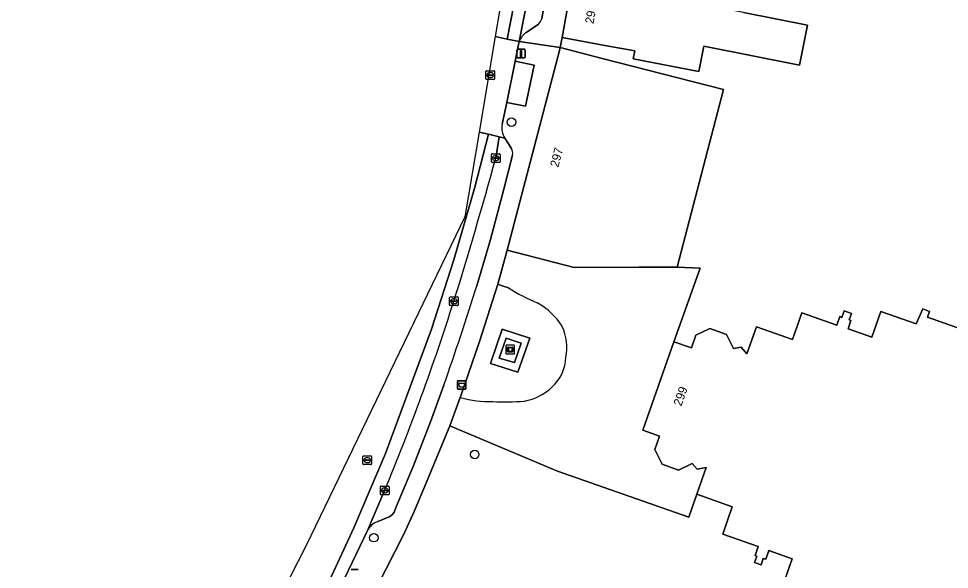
# Model space of a CAD drawing. Extents: x 160157 to 160921, y 381516 to 382045.
# Drawn here: x 160221.3 to 160328.3, y 381786.4 to 381849.8 of the extents above; entities that cross this region are included whole.
import ezdxf

# ---------------------------------------------------------------- set-up
doc = ezdxf.new("R2010")
doc.units = 0
for name, color, linetype in [('IMGEO_Afvalbak', 7, 'Continuous'), ('IMGEO_Boom', 7, 'Continuous'), ('IMGEO_Erf', 7, 'Continuous'), ('IMGEO_Grasland_overig', 7, 'Continuous'), ('IMGEO_Groenvoorziening', 7, 'Continuous'), ('IMGEO_Kolk', 7, 'Continuous'), ('IMGEO_Kunstobject', 7, 'Continuous'), ('IMGEO_Lichtmast', 7, 'Continuous'), ('IMGEO_Muur', 7, 'Continuous'), ('IMGEO_Pand', 7, 'Continuous'), ('IMGEO_Pand_nummerreeks', 7, 'Continuous'), ('IMGEO_Parkeervlak_open', 7, 'Continuous'), ('IMGEO_Rijbaan_lokaal_gesloten', 7, 'Continuous'), ('IMGEO_Rijbaan_lokaal_open', 7, 'Continuous'), ('IMGEO_Rioolput', 7, 'Continuous'), ('IMGEO_Terreindeel_gesloten', 7, 'Continuous'), ('IMGEO_Voetpad_open', 7, 'Continuous')]:
    doc.layers.add(name, color=color, linetype=linetype)

msp = doc.modelspace()

# ---------------------------------------------------------------- linework, layer by layer
at = {"layer": 'IMGEO_Afvalbak'}
for p, q in [((160271.85, 381808.13), (160272.64, 381808.13)), ((160272.64, 381808.13), (160271.85, 381808.13)), ((160271.75, 381807.24), (160271.75, 381808.03)), ((160271.75, 381808.03), (160271.75, 381807.24)), ((160272.64, 381807.14), (160271.85, 381807.14)), ((160271.85, 381807.14), (160272.64, 381807.14)), ((160272.74, 381808.03), (160272.74, 381807.24)), ((160272.74, 381807.24), (160272.74, 381808.03))]:
    msp.add_line(p, q, dxfattribs=at)
msp.add_lwpolyline([(160271.89, 381807.85), (160272.6, 381807.85), (160272.45, 381807.38), (160272.04, 381807.38), (160271.89, 381807.85)], dxfattribs=at)
for centre, start, end in [((160271.85, 381808.03), 90, 180), ((160271.85, 381808.03), 90, 180), ((160272.64, 381808.03), 0, 90), ((160272.64, 381808.03), 360, 90), ((160271.85, 381807.24), 180, 270), ((160271.85, 381807.24), 180, 270), ((160272.64, 381807.24), 270, 0), ((160272.64, 381807.24), 270, 0)]:
    msp.add_arc(centre, 0.1, start, end, dxfattribs=at)
at = {"layer": 'IMGEO_Boom'}
for centre in [(160277.98, 381837.86), (160273.74, 381799.65), (160262.15, 381790.08)]:
    msp.add_circle(centre, 0.489, dxfattribs=at)
at = {"layer": 'IMGEO_Erf'}
for points in [[(160304.64, 381850.46), (160311.98, 381849.02), (160311.07, 381844.42), (160300.06, 381846.58), (160299.49, 381843.66), (160291.95, 381845.14), (160292.13, 381846.07), (160288.71, 381846.67), (160283.79, 381847.6), (160283.57, 381846.42), (160288.39, 381845.18), (160302.32, 381841.61), (160297.01, 381821.2), (160299.65, 381821.06), (160296.64, 381812.6), (160298.66, 381811.9), (160299.17, 381813.36), (160300.78, 381814.13), (160302.69, 381813.46), (160303.48, 381811.83), (160304.36, 381812), (160305.03, 381811.22), (160306.12, 381814.32), (160310.27, 381812.86), (160311.35, 381815.94), (160315.36, 381814.53), (160315.7, 381815.5), (160315.95, 381815.41), (160316.21, 381816.16), (160317.04, 381815.86), (160316.79, 381815.13), (160316.99, 381815.06), (160316.65, 381814.08), (160319.39, 381813.12), (160320.43, 381816.08), (160324.47, 381814.66), (160325.23, 381816.38), (160326.02, 381816.1), (160325.79, 381815.43), (160330.23, 381813.88)], [(160309.15, 381784.6), (160310.23, 381787.66), (160307.54, 381788.6), (160307.19, 381787.6), (160306.9, 381787.7), (160306.65, 381786.98), (160305.9, 381787.24), (160306.15, 381787.96), (160305.96, 381788.04), (160306.32, 381789.07), (160302.25, 381790.5), (160303.35, 381793.64), (160299.27, 381795.07), (160298.35, 381792.45), (160283.25, 381797.74), (160270.9, 381802.95), (160268.19, 381796.46), (160266.77, 381793.11), (160265.61, 381790.49), (160253.12, 381765.96)]]:
    msp.add_lwpolyline(points, dxfattribs=at)
at = {"layer": 'IMGEO_Grasland_overig'}
for points in [[(160280.06, 381813.02), (160276.91, 381814.07), (160275.57, 381810.11), (160278.71, 381809.13)], [(160278.32, 381810.22), (160276.57, 381810.73), (160277.36, 381813.02), (160279.1, 381812.44)]]:
    msp.add_lwpolyline(points, close=True, dxfattribs=at)
at = {"layer": 'IMGEO_Groenvoorziening'}
msp.add_lwpolyline([(160277.62, 381818.81), (160276.91, 381819.04), (160276.39, 381819.22), (160274.31, 381812.62), (160272.16, 381806.4), (160272.09, 381806.2)], dxfattribs=at)
msp.add_lwpolyline([(160278.71, 381809.13), (160275.57, 381810.11), (160276.91, 381814.07), (160280.06, 381813.02)], close=True, dxfattribs=at)
for centre, radius, start, end in [((160290.22, 381838.73), 23.57, 237.6808, 246.7935), ((160277.27, 381810.3), 7.7, 32.0173, 61.5728), ((160278.48, 381811.97), 5.84, 348.6439, 24.3229), ((160279.41, 381810.97), 4.8, 312.6367, 358.2842), ((160278.4, 381811.79), 6.09, 279.9736, 314.4215), ((160275.63, 381819.2), 13.47, 254.7813, 270.825), ((160277.11, 381835.99), 30.29, 267.5557, 274.4318)]:
    msp.add_arc(centre, radius, start, end, dxfattribs=at)
at = {"layer": 'IMGEO_Kolk'}
for p, q in [((160275.66, 381833.28), (160275.66, 381834.14)), ((160275.74, 381834.21), (160276.59, 381834.21)), ((160276.15, 381833.99), (160276.18, 381833.99)), ((160276.66, 381834.14), (160276.66, 381833.28)), ((160276.59, 381833.21), (160275.74, 381833.21)), ((160275.92, 381833.7), (160275.92, 381833.72)), ((160276.36, 381833.67), (160275.96, 381833.67)), ((160275.97, 381833.75), (160276.36, 381833.75)), ((160276.17, 381833.43), (160276.15, 381833.43)), ((160276.41, 381833.72), (160276.41, 381833.7)), ((160270.93, 381817.76), (160271.78, 381817.76)), ((160270.85, 381816.84), (160270.85, 381817.69)), ((160271.78, 381816.76), (160270.93, 381816.76)), ((160271.11, 381817.26), (160271.11, 381817.27)), ((160271.15, 381817.31), (160271.55, 381817.31)), ((160271.55, 381817.22), (160271.15, 381817.22)), ((160271.34, 381817.54), (160271.36, 381817.54)), ((160271.36, 381816.98), (160271.34, 381816.98)), ((160271.59, 381817.27), (160271.59, 381817.26)), ((160271.85, 381817.69), (160271.85, 381816.84)), ((160262.9, 381795.09), (160262.9, 381795.94)), ((160262.97, 381796.02), (160263.83, 381796.02)), ((160263.16, 381795.51), (160263.16, 381795.52)), ((160263.2, 381795.56), (160263.6, 381795.56)), ((160263.59, 381795.47), (160263.2, 381795.47)), ((160263.39, 381795.8), (160263.41, 381795.8)), ((160263.64, 381795.52), (160263.64, 381795.51)), ((160263.9, 381795.94), (160263.9, 381795.09)), ((160263.83, 381795.02), (160262.97, 381795.02)), ((160263.41, 381795.24), (160263.38, 381795.24))]:
    msp.add_line(p, q, dxfattribs=at)
for points in [[(160275.66, 381833.28), (160275.66, 381834.14)], [(160275.74, 381834.21), (160276.59, 381834.21)], [(160276.66, 381834.14), (160276.66, 381833.28)], [(160276.59, 381833.21), (160275.74, 381833.21)], [(160270.93, 381817.76), (160271.78, 381817.76)], [(160270.85, 381816.84), (160270.85, 381817.69)], [(160271.78, 381816.76), (160270.93, 381816.76)], [(160271.85, 381817.69), (160271.85, 381816.84)], [(160262.9, 381795.09), (160262.9, 381795.94)], [(160262.97, 381796.02), (160263.83, 381796.02)], [(160263.9, 381795.94), (160263.9, 381795.09)], [(160263.83, 381795.02), (160262.97, 381795.02)]]:
    msp.add_lwpolyline(points, dxfattribs=at)
for centre, radius, start, end in [((160275.74, 381834.14), 0.0765, 91.552, 178.448), ((160275.74, 381834.14), 0.0765, 91.552, 178.448), ((160276.59, 381834.14), 0.0765, 1.552, 88.448), ((160276.59, 381834.14), 0.0765, 1.552, 88.448), ((160275.74, 381833.29), 0.0765, 181.552, 268.448), ((160275.74, 381833.29), 0.0765, 181.552, 268.448), ((160275.96, 381833.71), 0.0403, 85.8775, 175.7526), ((160275.96, 381833.7), 0.0366, 178.938, 274.7102), ((160276.37, 381833.72), 0.0386, 1.7309, 96.639), ((160276.36, 381833.71), 0.043, 264.8664, 352.4533), ((160276.59, 381833.29), 0.0765, 271.552, 358.448), ((160276.59, 381833.29), 0.0765, 271.552, 358.448), ((160270.93, 381817.69), 0.0765, 91.552, 178.448), ((160270.93, 381817.69), 0.0765, 91.552, 178.448), ((160271.78, 381817.69), 0.0765, 1.552, 88.448), ((160271.78, 381817.69), 0.0765, 1.552, 88.448), ((160270.93, 381816.84), 0.0765, 181.552, 268.448), ((160270.93, 381816.84), 0.0765, 181.552, 268.448), ((160271.15, 381817.27), 0.0403, 85.8775, 175.7526), ((160271.15, 381817.26), 0.0366, 178.938, 274.7102), ((160271.56, 381817.27), 0.0386, 1.7309, 96.639), ((160271.55, 381817.26), 0.043, 264.8664, 352.4533), ((160271.78, 381816.84), 0.0765, 271.552, 358.448), ((160271.78, 381816.84), 0.0765, 271.552, 358.448), ((160262.97, 381795.94), 0.0765, 91.552, 178.448), ((160262.97, 381795.94), 0.0765, 91.552, 178.448), ((160263.2, 381795.52), 0.0403, 85.8775, 175.7526), ((160263.19, 381795.51), 0.0366, 178.938, 274.7102), ((160263.6, 381795.52), 0.043, 264.8664, 352.4533), ((160263.6, 381795.52), 0.0386, 1.7309, 96.639), ((160263.82, 381795.94), 0.0765, 1.552, 88.448), ((160263.82, 381795.94), 0.0765, 1.552, 88.448), ((160262.97, 381795.09), 0.0765, 181.552, 268.448), ((160262.97, 381795.09), 0.0765, 181.552, 268.448), ((160263.82, 381795.09), 0.0765, 271.552, 358.448), ((160263.82, 381795.09), 0.0765, 271.552, 358.448)]:
    msp.add_arc(centre, radius, start, end, dxfattribs=at)
for centre, major_axis, ratio, start_param, end_param in [((160276.15, 381833.71), (-0.387, 0.002), 0.722429, 4.712389, 7.853982), ((160276.17, 381833.71), (-0.39, 0.002), 0.717154, 1.570796, 4.712389), ((160271.34, 381817.26), (-0.387, 0.002), 0.722429, 4.712389, 7.853982), ((160271.36, 381817.26), (-0.39, 0.002), 0.717154, 1.570796, 4.712389), ((160263.39, 381795.52), (-0.387, 0.002), 0.722429, 4.712389, 7.853982), ((160263.41, 381795.52), (-0.39, 0.002), 0.717154, 1.570796, 4.712389)]:
    msp.add_ellipse(centre, major_axis=major_axis, ratio=ratio, start_param=start_param, end_param=end_param, dxfattribs=at)
at = {"layer": 'IMGEO_Kunstobject'}
for p, q in [((160277.32, 381812.13), (160277.32, 381811.29)), ((160277.32, 381812.13), (160277.32, 381811.29)), ((160278.24, 381812.21), (160277.4, 381812.21)), ((160278.24, 381812.21), (160277.4, 381812.21)), ((160277.53, 381811.48), (160277.53, 381811.95)), ((160277.58, 381812), (160278.06, 381812)), ((160278.06, 381811.43), (160277.58, 381811.43)), ((160277.61, 381811.9), (160277.61, 381811.53)), ((160278.01, 381811.92), (160277.63, 381811.92)), ((160277.63, 381811.51), (160278.01, 381811.51)), ((160278.03, 381811.53), (160278.03, 381811.9)), ((160278.11, 381811.95), (160278.11, 381811.48)), ((160278.32, 381811.3), (160278.32, 381812.14)), ((160278.32, 381811.3), (160278.32, 381812.14)), ((160277.41, 381811.21), (160278.25, 381811.21)), ((160277.41, 381811.21), (160278.25, 381811.21))]:
    msp.add_line(p, q, dxfattribs=at)
for centre, radius, start, end in [((160277.4, 381812.13), 0.0779, 92.4484, 184.2845), ((160277.4, 381812.13), 0.0779, 92.4484, 184.2845), ((160277.58, 381811.95), 0.05, 90, 180), ((160277.58, 381811.48), 0.05, 180, 270), ((160277.63, 381811.9), 0.02, 90, 180), ((160277.63, 381811.53), 0.02, 180, 270), ((160278.01, 381811.9), 0.02, 360, 90), ((160278.01, 381811.53), 0.02, 270, 0), ((160278.06, 381811.95), 0.05, 360, 90), ((160278.06, 381811.48), 0.05, 270, 0), ((160278.24, 381812.13), 0.0779, 2.4484, 94.2845), ((160278.24, 381812.13), 0.0779, 2.4484, 94.2845), ((160277.4, 381811.29), 0.0779, 182.4484, 274.2845), ((160277.4, 381811.29), 0.0779, 182.4484, 274.2845), ((160278.24, 381811.29), 0.0779, 272.4484, 4.2845), ((160278.24, 381811.29), 0.0779, 272.4484, 4.2845)]:
    msp.add_arc(centre, radius, start, end, dxfattribs=at)
at = {"layer": 'IMGEO_Lichtmast'}
for p, q in [((160278.57, 381845.34), (160278.57, 381846.13)), ((160278.57, 381846.13), (160278.57, 381845.34)), ((160278.67, 381846.23), (160279.46, 381846.23)), ((160279.46, 381846.23), (160278.67, 381846.23)), ((160279.56, 381846.13), (160279.56, 381845.34)), ((160279.56, 381845.34), (160279.56, 381846.13)), ((160279.46, 381845.24), (160278.67, 381845.24)), ((160278.67, 381845.24), (160279.46, 381845.24)), ((160259.56, 381786.44), (160260.34, 381786.44)), ((160260.34, 381786.44), (160259.56, 381786.44))]:
    msp.add_line(p, q, dxfattribs=at)
msp.add_lwpolyline([(160278.99, 381846.11), (160279.14, 381846.11), (160279.14, 381845.36), (160278.99, 381845.36), (160278.99, 381846.11)], dxfattribs=at)
for centre, start, end in [((160278.67, 381846.13), 90, 180), ((160278.67, 381846.13), 90, 180), ((160279.46, 381846.13), 0, 90), ((160279.46, 381846.13), 360, 90), ((160278.67, 381845.34), 180, 270), ((160278.67, 381845.34), 180, 270), ((160279.46, 381845.34), 270, 0), ((160279.46, 381845.34), 270, 0)]:
    msp.add_arc(centre, 0.1, start, end, dxfattribs=at)
at = {"layer": 'IMGEO_Muur'}
for points in [[(160276.39, 381819.22), (160274.31, 381812.62), (160272.16, 381806.4), (160272.09, 381806.2)], [(160268.19, 381796.46), (160270.9, 381802.95)], [(160253.12, 381765.96), (160265.61, 381790.49), (160266.77, 381793.11)]]:
    msp.add_lwpolyline(points, dxfattribs=at)
at = {"layer": 'IMGEO_Pand'}
for points in [[(160311.98, 381849.02), (160304.64, 381850.46), (160302.06, 381850.97), (160299.88, 381851.39), (160293.38, 381852.67), (160293.08, 381852.73), (160293.14, 381853.09), (160285.02, 381854.49), (160283.79, 381847.6), (160288.71, 381846.67), (160292.13, 381846.07), (160291.95, 381845.14), (160299.49, 381843.66), (160300.06, 381846.58), (160311.07, 381844.42)], [(160283.57, 381846.42), (160283.49, 381846.11), (160277.48, 381823.12), (160285.16, 381821.16), (160292.59, 381821.19), (160292.78, 381821.19), (160297.01, 381821.2), (160302.32, 381841.61), (160288.39, 381845.18)]]:
    msp.add_lwpolyline(points, close=True, dxfattribs=at)
msp.add_lwpolyline([(160330.23, 381813.88), (160325.79, 381815.43), (160326.02, 381816.1), (160325.23, 381816.38), (160324.47, 381814.66), (160320.43, 381816.08), (160319.39, 381813.12), (160316.65, 381814.08), (160316.99, 381815.06), (160316.79, 381815.13), (160317.04, 381815.86), (160316.21, 381816.16), (160315.95, 381815.41), (160315.7, 381815.5), (160315.36, 381814.53), (160311.35, 381815.94), (160310.27, 381812.86), (160306.12, 381814.32), (160305.03, 381811.22), (160304.36, 381812), (160303.48, 381811.83), (160302.69, 381813.46), (160300.78, 381814.13), (160299.17, 381813.36), (160298.66, 381811.9), (160296.64, 381812.6), (160293.07, 381802.43), (160295, 381801.75), (160294.46, 381800.23), (160295.29, 381798.52), (160297.15, 381797.86), (160298.74, 381798.62), (160299.31, 381797.96), (160300.35, 381798.15), (160299.27, 381795.07), (160303.35, 381793.64), (160302.25, 381790.5), (160306.32, 381789.07), (160305.96, 381788.04), (160306.15, 381787.96), (160305.9, 381787.24), (160306.65, 381786.98), (160306.9, 381787.7), (160307.19, 381787.6), (160307.54, 381788.6), (160310.23, 381787.66), (160309.15, 381784.6)], dxfattribs=at)
at = {"layer": 'IMGEO_Parkeervlak_open'}
for points in [[(160282.32, 381865.78), (160280.45, 381855.34), (160278.87, 381847.11)], [(160281.46, 381849.76), (160283.72, 381862.41)], [(160279.73, 381848.2), (160281.07, 381849.13)], [(160277.96, 381834.84), (160277.19, 381836.03), (160276.55, 381836.18), (160276.16, 381833.71)], [(160273.97, 381819.05), (160275.56, 381824.35), (160277.11, 381830.16), (160278.08, 381834.07)], [(160262.53, 381791.92), (160263.93, 381792.5), (160264.25, 381792.73), (160264.49, 381793.02), (160264.73, 381793.62), (160266.66, 381798.25), (160268.65, 381803.39), (160270.19, 381807.62)], [(160263.39, 381795.52), (160261.41, 381790.91)]]:
    msp.add_lwpolyline(points, dxfattribs=at)
msp.add_lwpolyline([(160280.57, 381844.42), (160278.4, 381844.86), (160277.43, 381840.12), (160279.58, 381839.7)], close=True, dxfattribs=at)
for centre, radius, start, end in [((160280.38, 381849.99), 1.1, 308.3584, 347.7613), ((160280.85, 381846.44), 2.09, 122.4168, 161.2549), ((160277.16, 381834.31), 0.951, 345.1327, 33.6957), ((159797.9, 381964.7), 495.87, 342.7026, 344.6829), ((159969.33, 381913.56), 318.97, 340.603, 342.7649), ((160017.57, 381897.75), 266.23, 337.4183, 342.4028), ((160263.35, 381789.88), 2.19, 111.9125, 151.9314)]:
    msp.add_arc(centre, radius, start, end, dxfattribs=at)
at = {"layer": 'IMGEO_Rijbaan_lokaal_gesloten'}
for points in [[(160276.11, 381847.71), (160277.47, 381847.41), (160279.43, 381857.4), (160281.06, 381866.83), (160283.01, 381877.48), (160287.95, 381901.47), (160291.03, 381915.39), (160292.66, 381923.46), (160295.11, 381937.88), (160297.52, 381953.39), (160298.83, 381953.2), (160299.47, 381957.15), (160299.62, 381958.1), (160298.28, 381958.32), (160297.16, 381958.5), (160297.16, 381958.5), (160296.82, 381956.93), (160291.86, 381933.88), (160277.86, 381858.1)], [(160221.32, 381724.92), (160224.38, 381723.35), (160226.13, 381726.77), (160238.68, 381750.08), (160245.71, 381763.32), (160252.51, 381776.06), (160256.59, 381784.17), (160259.85, 381791.2), (160263.48, 381799.77), (160268.78, 381814.05), (160271.36, 381822.03), (160273.77, 381830.38), (160275.32, 381836.47), (160274.26, 381836.72), (160274.26, 381836.72), (160272.62, 381826.97), (160254.37, 381789.2), (160234.62, 381750.43)]]:
    msp.add_lwpolyline(points, close=True, dxfattribs=at)
for points in [[(160279.43, 381857.4), (160277.47, 381847.41), (160278.87, 381847.11), (160280.45, 381855.34)], [(160276.91, 381837.61), (160277.43, 381840.12), (160278.4, 381844.86), (160278.83, 381846.97), (160278.87, 381847.11), (160277.47, 381847.41), (160276.11, 381847.71), (160274.26, 381836.72)], [(160276.16, 381833.71), (160276.55, 381836.18), (160275.32, 381836.47), (160273.77, 381830.38), (160271.36, 381822.03), (160268.78, 381814.05), (160263.48, 381799.77), (160259.85, 381791.2), (160256.59, 381784.17), (160252.51, 381776.06), (160245.71, 381763.32), (160238.68, 381750.08), (160226.13, 381726.77), (160224.38, 381723.35), (160225.65, 381722.7), (160227.87, 381726.9), (160234.08, 381738.56), (160237.37, 381744.72), (160239.23, 381748.15), (160240.22, 381750), (160248.02, 381764.54)], [(160274.26, 381836.72), (160274.26, 381836.72), (160275.32, 381836.47), (160276.55, 381836.18), (160277.19, 381836.03)], [(160248.02, 381764.54), (160254.74, 381777.2), (160257.05, 381781.79), (160261.41, 381790.91), (160263.39, 381795.52)]]:
    msp.add_lwpolyline(points, dxfattribs=at)
for centre, radius, start, end in [((160278.92, 381837.14), 2.06, 167.0279, 212.7345), ((159797.9, 381964.7), 495.87, 342.7026, 344.6829), ((160017.57, 381897.75), 266.23, 337.4183, 342.4028)]:
    msp.add_arc(centre, radius, start, end, dxfattribs=at)
at = {"layer": 'IMGEO_Rijbaan_lokaal_open'}
for points in [[(160296.64, 381812.6), (160299.65, 381821.06), (160297.01, 381821.2), (160292.78, 381821.19), (160292.59, 381821.19), (160285.16, 381821.16), (160277.48, 381823.12), (160276.39, 381819.22), (160276.91, 381819.04), (160277.62, 381818.81)], [(160272.09, 381806.2), (160270.9, 381802.95), (160283.25, 381797.74), (160298.35, 381792.45), (160299.27, 381795.07), (160300.35, 381798.15), (160299.31, 381797.96), (160298.74, 381798.62), (160297.15, 381797.86), (160295.29, 381798.52), (160294.46, 381800.23), (160295, 381801.75), (160293.07, 381802.43), (160296.64, 381812.6)]]:
    msp.add_lwpolyline(points, dxfattribs=at)
for centre, radius, start, end in [((160290.22, 381838.73), 23.57, 237.6808, 246.7935), ((160277.27, 381810.3), 7.7, 32.0173, 61.5728), ((160278.48, 381811.97), 5.84, 348.6439, 24.3229), ((160279.41, 381810.97), 4.8, 312.6367, 358.2842), ((160278.4, 381811.79), 6.09, 279.9736, 314.4215), ((160275.63, 381819.2), 13.47, 254.7813, 270.825), ((160277.11, 381835.99), 30.29, 267.5557, 274.4318)]:
    msp.add_arc(centre, radius, start, end, dxfattribs=at)
at = {"layer": 'IMGEO_Rioolput'}
for p, q in [((160275.03, 381842.84), (160275.03, 381843.7)), ((160275.1, 381843.77), (160275.95, 381843.77)), ((160275.51, 381843.55), (160275.54, 381843.55)), ((160276.03, 381843.7), (160276.03, 381842.84)), ((160275.95, 381842.77), (160275.1, 381842.77)), ((160275.28, 381843.26), (160275.28, 381843.28)), ((160275.72, 381843.23), (160275.32, 381843.23)), ((160275.33, 381843.31), (160275.73, 381843.31)), ((160275.54, 381842.99), (160275.51, 381842.99)), ((160275.77, 381843.28), (160275.77, 381843.26)), ((160260.89, 381798.56), (160260.89, 381799.42)), ((160260.96, 381799.49), (160261.82, 381799.49)), ((160261.82, 381798.49), (160260.96, 381798.49)), ((160261.15, 381798.98), (160261.15, 381799)), ((160261.19, 381799.03), (160261.59, 381799.03)), ((160261.59, 381798.95), (160261.19, 381798.95)), ((160261.4, 381798.71), (160261.37, 381798.71)), ((160261.38, 381799.27), (160261.4, 381799.27)), ((160261.63, 381799), (160261.63, 381798.98)), ((160261.89, 381799.42), (160261.89, 381798.56))]:
    msp.add_line(p, q, dxfattribs=at)
for points in [[(160275.03, 381842.84), (160275.03, 381843.7)], [(160275.1, 381843.77), (160275.95, 381843.77)], [(160276.03, 381843.7), (160276.03, 381842.84)], [(160275.95, 381842.77), (160275.1, 381842.77)], [(160260.89, 381798.56), (160260.89, 381799.42)], [(160260.96, 381799.49), (160261.82, 381799.49)], [(160261.82, 381798.49), (160260.96, 381798.49)], [(160261.89, 381799.42), (160261.89, 381798.56)]]:
    msp.add_lwpolyline(points, dxfattribs=at)
for centre, radius, start, end in [((160275.1, 381843.69), 0.0765, 91.552, 178.448), ((160275.1, 381843.69), 0.0765, 91.552, 178.448), ((160275.95, 381843.69), 0.0765, 1.552, 88.448), ((160275.95, 381843.69), 0.0765, 1.552, 88.448), ((160275.1, 381842.84), 0.0765, 181.552, 268.448), ((160275.1, 381842.84), 0.0765, 181.552, 268.448), ((160275.33, 381843.27), 0.0403, 85.8775, 175.7526), ((160275.32, 381843.26), 0.0366, 178.938, 274.7102), ((160275.73, 381843.27), 0.043, 264.8664, 352.4533), ((160275.73, 381843.27), 0.0386, 1.7309, 96.639), ((160275.95, 381842.84), 0.0765, 271.552, 358.448), ((160275.95, 381842.84), 0.0765, 271.552, 358.448), ((160260.97, 381799.41), 0.0765, 91.552, 178.448), ((160260.97, 381799.41), 0.0765, 91.552, 178.448), ((160260.97, 381798.57), 0.0765, 181.552, 268.448), ((160260.97, 381798.57), 0.0765, 181.552, 268.448), ((160261.19, 381798.99), 0.0403, 85.8775, 175.7526), ((160261.18, 381798.98), 0.0366, 178.938, 274.7102), ((160261.59, 381798.99), 0.0386, 1.7309, 96.639), ((160261.59, 381798.99), 0.043, 264.8664, 352.4533), ((160261.81, 381799.41), 0.0765, 1.552, 88.448), ((160261.81, 381799.41), 0.0765, 1.552, 88.448), ((160261.81, 381798.57), 0.0765, 271.552, 358.448), ((160261.81, 381798.57), 0.0765, 271.552, 358.448)]:
    msp.add_arc(centre, radius, start, end, dxfattribs=at)
for centre, major_axis, ratio, start_param, end_param in [((160275.51, 381843.27), (-0.387, 0.002), 0.722429, 4.712389, 7.853982), ((160275.54, 381843.27), (-0.39, 0.002), 0.717154, 1.570796, 4.712389), ((160261.38, 381798.99), (-0.387, 0.002), 0.722429, 4.712389, 7.853982), ((160261.4, 381798.99), (-0.39, 0.002), 0.717154, 1.570796, 4.712389)]:
    msp.add_ellipse(centre, major_axis=major_axis, ratio=ratio, start_param=start_param, end_param=end_param, dxfattribs=at)
at = {"layer": 'IMGEO_Terreindeel_gesloten'}
msp.add_lwpolyline([(160279.1, 381812.44), (160277.36, 381813.02), (160276.57, 381810.73), (160278.32, 381810.22)], close=True, dxfattribs=at)
at = {"layer": 'IMGEO_Voetpad_open'}
for points in [[(160278.87, 381847.11), (160283.57, 381846.42), (160283.79, 381847.6), (160285.02, 381854.49), (160286.02, 381860.07), (160287.61, 381869.03), (160288.21, 381872.12), (160287.24, 381872.28), (160288.45, 381879.49), (160289.61, 381886.39), (160290.73, 381893.02), (160291.91, 381900.02), (160292.84, 381906.61)], [(160283.72, 381862.41), (160281.46, 381849.76)], [(160281.07, 381849.13), (160279.73, 381848.2)], [(160265.61, 381790.49), (160266.77, 381793.11), (160268.19, 381796.46), (160270.9, 381802.95), (160272.09, 381806.2), (160272.16, 381806.4), (160274.31, 381812.62), (160276.39, 381819.22), (160277.48, 381823.12), (160283.49, 381846.11), (160283.57, 381846.42), (160278.87, 381847.11), (160278.83, 381846.97), (160278.4, 381844.86), (160280.57, 381844.42), (160279.58, 381839.7), (160277.43, 381840.12), (160276.91, 381837.61)], [(160277.19, 381836.03), (160277.96, 381834.84)], [(160278.08, 381834.07), (160277.11, 381830.16), (160275.56, 381824.35), (160273.97, 381819.05)], [(160270.19, 381807.62), (160268.65, 381803.39), (160266.66, 381798.25), (160264.73, 381793.62), (160264.49, 381793.02), (160264.25, 381792.73), (160263.93, 381792.5), (160262.53, 381791.92)], [(160265.65, 381723.16), (160238.18, 381739.31), (160240.05, 381742.14), (160242.54, 381745.85), (160242.62, 381745.95), (160242.75, 381745.86), (160242.91, 381746.14), (160243.9, 381748.1), (160245.7, 381751.66), (160251.51, 381762.79), (160253.12, 381765.96), (160265.61, 381790.49)], [(160261.41, 381790.91), (160257.05, 381781.79)]]:
    msp.add_lwpolyline(points, dxfattribs=at)
for centre, radius, start, end in [((160280.38, 381849.99), 1.1, 308.3584, 347.7613), ((160280.85, 381846.44), 2.09, 122.4168, 161.2549), ((160278.92, 381837.14), 2.06, 167.0279, 212.7345), ((160277.16, 381834.31), 0.951, 345.1327, 33.6957), ((159969.33, 381913.56), 318.97, 340.603, 342.7649), ((160263.35, 381789.88), 2.19, 111.9125, 151.9314)]:
    msp.add_arc(centre, radius, start, end, dxfattribs=at)

# ---------------------------------------------------------------- texts
at = {"layer": 'IMGEO_Pand_nummerreeks'}
for s, rotation, p in [('295', 79.8875, (160287.39, 381849.11)), ('297', 75.3554, (160283.35, 381832.61)), ('299', 70.6781, (160297.49, 381805.13))]:
    msp.add_text(s, height=1, rotation=rotation, dxfattribs=at).set_placement(p)

doc.saveas('drawing.dxf')
